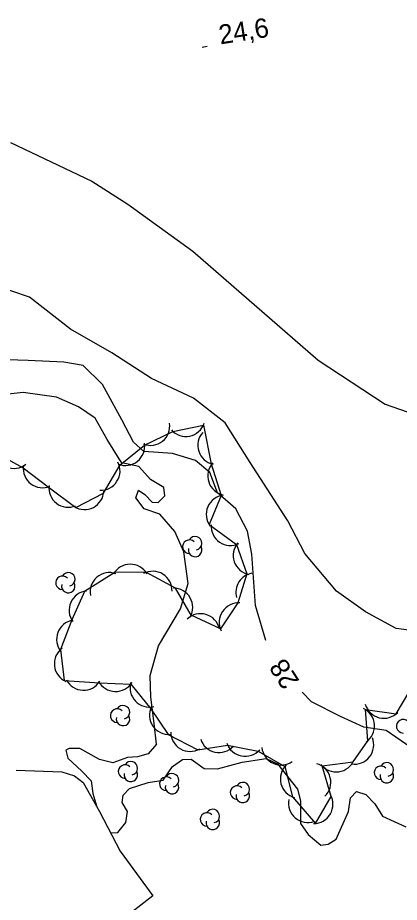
# Model space of a CAD drawing. Extents: x 646142 to 649934, y 5874075 to 5876351.
# Drawn here: x 648290.8 to 648350.1, y 5875382.2 to 5875519.6 of the extents above; entities that cross this region are included whole.
import ezdxf

# ---------------------------------------------------------------- set-up
doc = ezdxf.new("R2010")
doc.units = 0
for name, color, linetype in [('Niveau 1', 7, 'Continuous'), ('Niveau 19', 7, 'Continuous'), ('Niveau 2', 7, 'Continuous'), ('Niveau 3', 7, 'Continuous'), ('Niveau 4', 7, 'Continuous'), ('Niveau 44', 7, 'Continuous')]:
    doc.layers.add(name, color=color, linetype=linetype)

msp = doc.modelspace()

# ---------------------------------------------------------------- linework, layer by layer
at = {"layer": 'Niveau 1'}
for points in [[(648312.37, 5875406.73), (648312.02, 5875409.97), (648311.48, 5875414.06), (648311.35, 5875417.38), (648312.65, 5875422.02), (648316.11, 5875427.75), (648317.3, 5875431.69), (648316.59, 5875436.63), (648315.21, 5875439.79), (648312.89, 5875442.47), (648310.43, 5875443.3), (648309.16, 5875444.98), (648309.58, 5875446.16), (648310.55, 5875445.5), (648311.67, 5875444.32), (648312.64, 5875444.29), (648313.65, 5875445.29), (648313.5, 5875446.59), (648311.4, 5875447.86), (648309.59, 5875449.84), (648306.98, 5875450.43), (648306.53, 5875451.03), (648304.71, 5875454.04), (648302.85, 5875457.39), (648300.26, 5875459.13), (648296.83, 5875460.63), (648291.63, 5875461.36), (648287.32, 5875460.9)], [(648312.37, 5875406.73), (648311.06, 5875405.24), (648309.43, 5875404.77), (648307.84, 5875404.69), (648305.56, 5875403.82), (648303.52, 5875404.34), (648300.42, 5875406.04), (648298.76, 5875406.08), (648298.26, 5875405.81), (648298.58, 5875404.57), (648300.74, 5875402.57), (648302.22, 5875401.02), (648302.48, 5875399.09), (648303.07, 5875397.03)], [(648305.2, 5875392.99), (648305.23, 5875392.95), (648306.37, 5875393.04), (648307.57, 5875394.57), (648307.84, 5875396.26), (648307.02, 5875397.68), (648307.16, 5875398.84), (648308.17, 5875399.84), (648311.08, 5875400.77), (648313.39, 5875401.13), (648314.83, 5875403.25), (648316.41, 5875404.36), (648317.75, 5875404.41), (648319.74, 5875402.96), (648321.86, 5875402.91), (648325.67, 5875403.96), (648329.4, 5875404.5), (648331.18, 5875403.66), (648334.28, 5875399.73), (648334.75, 5875397.93), (648334.73, 5875394.43), (648335.95, 5875392.69), (648337.9, 5875391.07), (648339.03, 5875391.22), (648340.28, 5875392.01), (648342.19, 5875396.3), (648342.49, 5875398.39), (648343.44, 5875399.38), (648344.91, 5875398.93), (648346.27, 5875397.49), (648347.5, 5875395.58), (648351.11, 5875393.92)]]:
    msp.add_lwpolyline(points, dxfattribs=at)
at = {"layer": 'Niveau 19'}
msp.add_lwpolyline([(648290.54, 5875402.69), (648297.65, 5875402.46), (648299.64, 5875401.82), (648300.98, 5875400.78), (648303.49, 5875396.28), (648306.7, 5875390.11), (648311.79, 5875383.18), (648298.29, 5875372.67), (648296.79, 5875369.79), (648304.78, 5875359.32), (648299.89, 5875359.03), (648292.96, 5875358.35), (648283.17, 5875356.17)], dxfattribs=at)
at = {"layer": 'Niveau 2'}
for points in [[(648354.74, 5875424.02), (648349.59, 5875424.7), (648344.81, 5875427.3), (648340.33, 5875430.51), (648335.42, 5875436.33), (648332.75, 5875441.41), (648326.91, 5875450.49), (648323.01, 5875456.63), (648318.13, 5875460.49), (648311.59, 5875463.54), (648305.44, 5875467.53), (648298.97, 5875471.16), (648292.63, 5875476.18), (648287.09, 5875478.04)], [(648329.33, 5875422.84), (648327.76, 5875428.25), (648327.16, 5875436.24), (648326.49, 5875439.81), (648324.68, 5875443.29), (648321.81, 5875445.76), (648320.65, 5875448.94), (648318.4, 5875450.77), (648314.82, 5875451.86), (648310.39, 5875452.19), (648308.79, 5875453.62), (648306.98, 5875457.09), (648303.94, 5875462.6), (648300.97, 5875465.52), (648297.95, 5875466.08), (648292.43, 5875466.33), (648285.94, 5875466.55), (648280.64, 5875467.62), (648277.56, 5875468.18), (648272.79, 5875468.47)], [(648376.16, 5875380.93), (648372.37, 5875382.68), (648370.1, 5875385.43), (648369.07, 5875387.81), (648366.67, 5875392.27), (648364.84, 5875394.59), (648362.07, 5875395), (648359.88, 5875395.97), (648358.97, 5875397.45), (648359.17, 5875400.05), (648358.39, 5875401.37), (648356.08, 5875403.82), (648352.56, 5875405.78), (648348.04, 5875408.86), (648344.57, 5875409.38), (648340.95, 5875411.04), (648336.43, 5875413.32), (648334.97, 5875414.79)]]:
    msp.add_lwpolyline(points, dxfattribs=at)
at = {"layer": 'Niveau 3'}
msp.add_line((648319.43, 5875515), (648320.22, 5875515.12), dxfattribs=at)
at = {"layer": 'Niveau 4'}
msp.add_lwpolyline([(648289.69, 5875500.17), (648302.31, 5875494.16), (648307.91, 5875490.59), (648317.99, 5875483.32), (648337.46, 5875466.39), (648347.88, 5875459.53), (648360.7, 5875455.08), (648370.76, 5875452.99), (648374.19, 5875453.19), (648376.74, 5875454.45), (648379.77, 5875458.07), (648395.21, 5875474.1), (648417.49, 5875494.21), (648422.47, 5875497.67), (648426.22, 5875498.5), (648431.78, 5875498.76), (648437.94, 5875498.71), (648447.65, 5875499.66), (648458.71, 5875500.56)], dxfattribs=at)
at = {"layer": 'Niveau 44'}
for points in [[(648287.18, 5875452.06), (648291.65, 5875449.64), (648295.51, 5875446.7), (648299.83, 5875443.48), (648304.14, 5875445.73), (648306.73, 5875450.12), (648310.51, 5875453.16), (648314.89, 5875455.31), (648319.65, 5875456.28), (648320.85, 5875450.29), (648322.42, 5875445.33), (648320.52, 5875440.87), (648324.81, 5875437.76), (648326.4, 5875433.18), (648324.99, 5875428.67), (648322.29, 5875424.64), (648317.75, 5875426.76), (648315.3, 5875430.95), (648310.71, 5875433.47), (648305.86, 5875433.42), (648301.16, 5875430.46), (648299.19, 5875426.03), (648297.46, 5875421.45), (648297.99, 5875416.62), (648303.52, 5875416.25), (648308.37, 5875416.07), (648311.46, 5875412.25), (648314.19, 5875408.24), (648318.8, 5875405.87), (648323.41, 5875406.6), (648328.17, 5875405.64), (648332.29, 5875403.25), (648333.5, 5875398.55), (648337.09, 5875394.42), (648339.52, 5875398.62), (648338.12, 5875403.36), (648342.93, 5875404)], [(648342.93, 5875404), (648345.18, 5875407.27), (648344.82, 5875412.11), (648349.62, 5875411.47), (648352.54, 5875416.42)]]:
    msp.add_lwpolyline(points, dxfattribs=at)
for centre, radius, start, end in [((648311.42, 5875456.14), 3, 248.7476, 8.7255), ((648316.92, 5875457.52), 3, 221.4445, 341.4224), ((648321.77, 5875453.15), 3, 138.111, 258.0889), ((648290.2, 5875452.57), 3, 187.9317, 307.9097), ((648307.52, 5875453.01), 3, 248.7476, 8.7255), ((648294.65, 5875449.57), 3, 172.6234, 292.6013), ((648303.69, 5875449.17), 3, 267.4522, 27.4302), ((648323.32, 5875448.4), 3, 138.111, 258.0889), ((648298.63, 5875446.53), 3, 172.6234, 292.6013), ((648301.17, 5875446.17), 3, 237.5584, 357.5364), ((648323.09, 5875442.41), 3, 96.9066, 216.8845), ((648323.84, 5875440.59), 3, 175.7541, 295.7321), ((648317.46, 5875437.41), 1.05, 44.1154, 269.804), ((648318.36, 5875437.94), 1.05, 282.2692, 149.7263), ((648318.36, 5875436.89), 1.05, 166.9369, 29.6212), ((648327.27, 5875436.05), 3, 139.1405, 259.1185), ((648308.3, 5875431.68), 3, 30.5896, 150.5676), ((648298.65, 5875432.34), 1.05, 282.2692, 149.7263), ((648305.03, 5875430.38), 3, 70.7253, 190.7033), ((648311.77, 5875430.59), 3, 358.0483, 118.0263), ((648327.69, 5875430.32), 3, 99.5475, 195.3058), ((648297.75, 5875431.81), 1.05, 44.1154, 269.804), ((648298.65, 5875431.29), 1.05, 166.9369, 29.6212), ((648301.78, 5875427.53), 3, 95.9785, 215.9564), ((648315, 5875427.97), 3, 330.2401, 90.2181), ((648325.11, 5875425.67), 3, 86.1772, 206.1552), ((648319.2, 5875424), 3, 13.6184, 133.5963), ((648299.83, 5875423.02), 3, 99.4329, 219.4109), ((648299.48, 5875419.23), 3, 126.2713, 246.2492), ((648301.01, 5875418.11), 3, 207.922, 327.9), ((648306.01, 5875417.92), 3, 207.922, 327.9), ((648311.24, 5875415.5), 3, 163.6457, 283.6236), ((648307.15, 5875411.7), 1.05, 282.2692, 149.7263), ((648314.28, 5875411.24), 3, 154.1907, 274.1686), ((648347.69, 5875413.76), 3, 196.1279, 316.1058), ((648306.25, 5875411.17), 1.05, 44.1154, 269.804), ((648307.15, 5875410.65), 1.05, 166.9369, 29.6212), ((648343.24, 5875409.56), 3, 304.3099, 64.2879), ((648350.69, 5875409.52), 1.05, 44.1154, 269.804), ((648317.57, 5875408.61), 3, 180.2456, 300.2235), ((648322.08, 5875408.44), 3, 197.6524, 317.6304), ((648326.14, 5875407.85), 3, 198.5831, 318.561), ((648343.11, 5875406.63), 3, 261.7044, 21.6823), ((648331.72, 5875406.5), 3, 185.4407, 305.4187), ((648308.37, 5875403.01), 1.05, 282.2692, 149.7263), ((648340.29, 5875405.43), 3, 217.6147, 337.5926), ((648307.47, 5875402.48), 1.05, 44.1154, 269.804), ((648334.6, 5875401.34), 3, 134.4446, 254.4226), ((648336.45, 5875400.81), 3, 313.8839, 73.8618), ((648347.25, 5875402.29), 1.05, 44.1154, 269.804), ((648348.15, 5875402.82), 1.05, 282.2692, 149.7263), ((648308.37, 5875401.96), 1.05, 166.9369, 29.6212), ((648313.87, 5875400.6), 1.05, 44.1154, 269.804), ((648314.77, 5875401.13), 1.05, 282.2692, 149.7263), ((648348.15, 5875401.77), 1.05, 166.9369, 29.6212), ((648314.77, 5875400.08), 1.05, 166.9369, 29.6212), ((648324.87, 5875399.22), 1.05, 44.1154, 269.804), ((648325.77, 5875399.75), 1.05, 282.2692, 149.7263), ((648325.77, 5875398.7), 1.05, 166.9369, 29.6212), ((648336.78, 5875397.4), 3, 269.8859, 29.8639), ((648335.88, 5875397.58), 3, 169.3874, 289.3653), ((648320.21, 5875395.05), 1.05, 44.1154, 269.804), ((648321.11, 5875395.58), 1.05, 282.2692, 149.7263), ((648321.11, 5875394.53), 1.05, 166.9369, 29.6212)]:
    msp.add_arc(centre, radius, start, end, dxfattribs=at)

# ---------------------------------------------------------------- texts
at = {"layer": 'Niveau 2'}
msp.add_text('28', height=3, rotation=122.687, dxfattribs=at).set_placement((648334.65, 5875416.56))
at = {"layer": 'Niveau 3'}
msp.add_text('24,6 ', height=3, rotation=8.9405, dxfattribs=at).set_placement((648322.28, 5875515.4))

doc.saveas('drawing.dxf')
